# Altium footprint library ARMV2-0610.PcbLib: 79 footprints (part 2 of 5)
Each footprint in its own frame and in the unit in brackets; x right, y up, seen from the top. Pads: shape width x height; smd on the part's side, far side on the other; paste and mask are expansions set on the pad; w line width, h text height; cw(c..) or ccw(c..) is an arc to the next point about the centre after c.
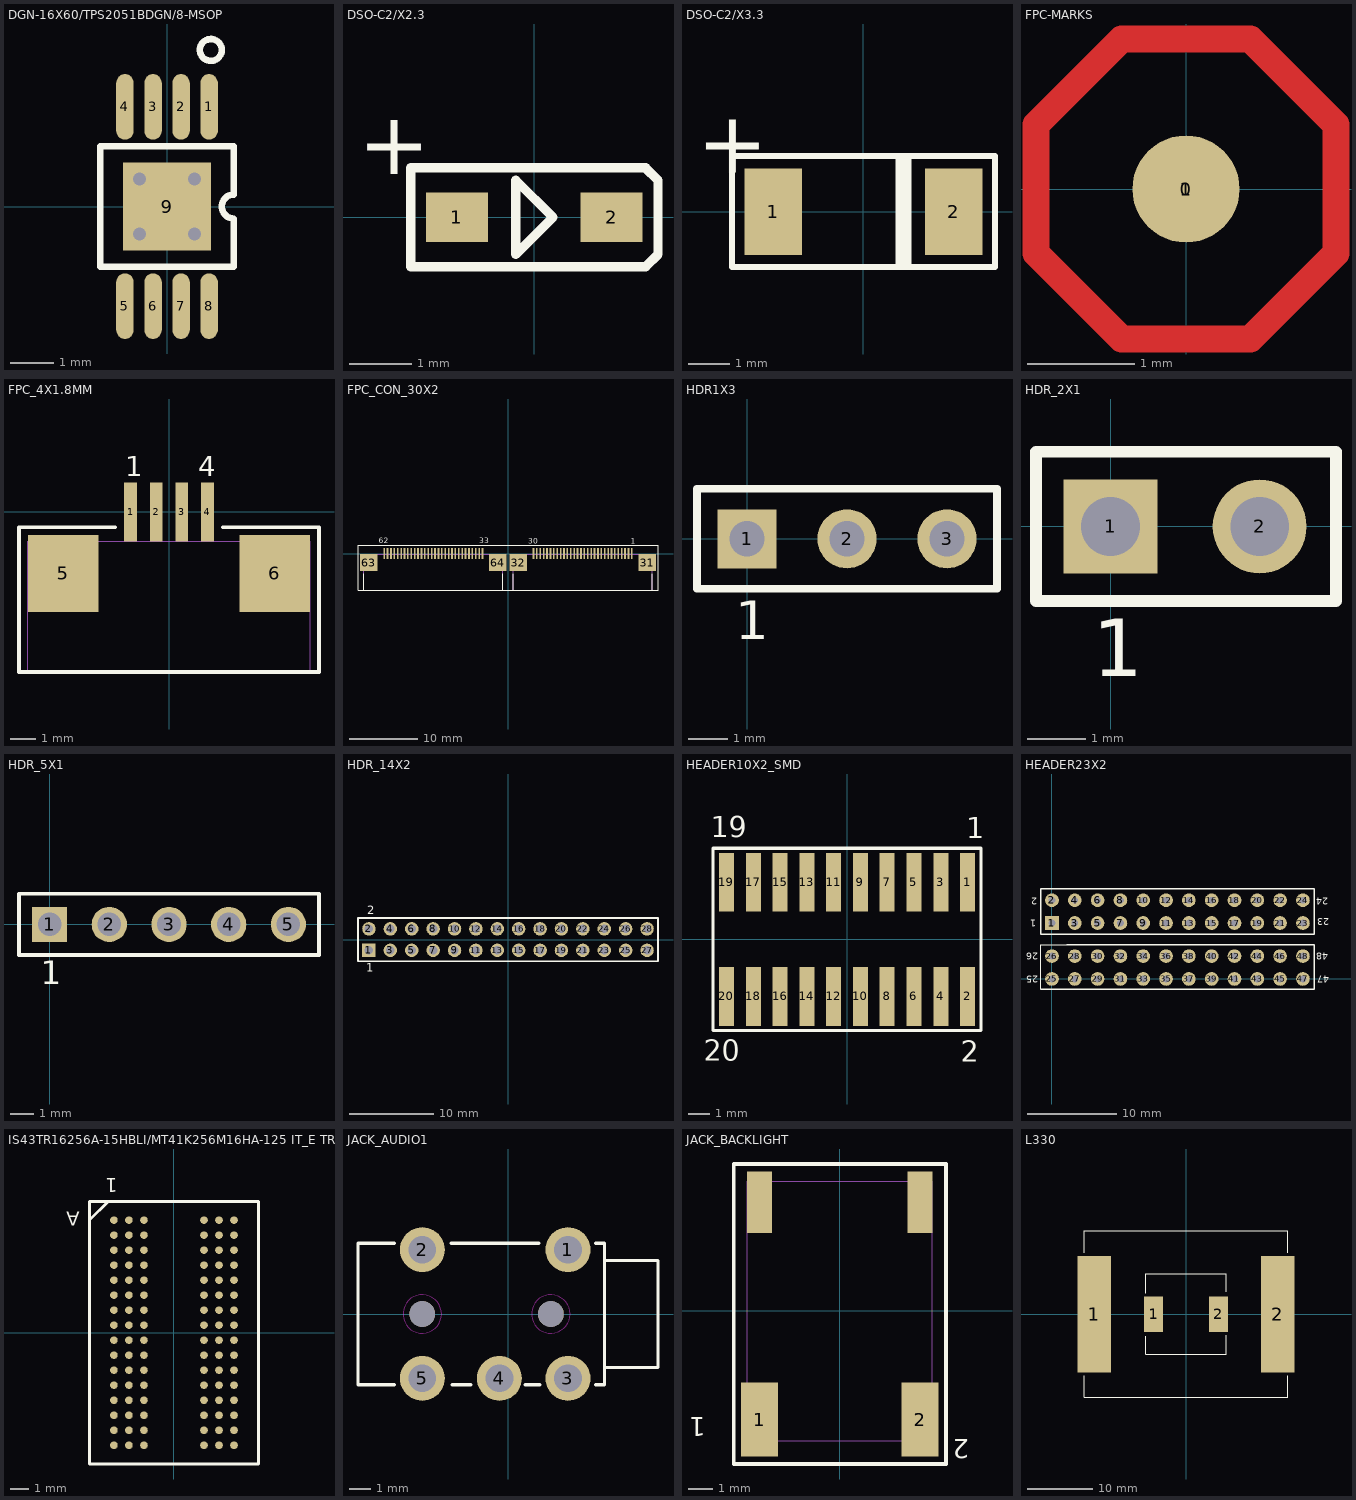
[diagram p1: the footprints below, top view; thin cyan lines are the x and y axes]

## DGN-16X60/TPS2051BDGN/8-MSOP [mil]
pads (9):
  oval 16x60 smd mask+2: 1(38.4,91) 2(12.8,91) 3(-12.8,91) 4(-38.4,91) 5(-38.4,-91) 6(-12.8,-91) 7(12.8,-91) 8(38.4,-91)
  rect 80x80 smd mask+2: 9(0,0)
via 25,25 diameter 22 hole 12
via -25,25 diameter 22 hole 12
via -25,-25 diameter 22 hole 12
via 25,-25 diameter 22 hole 12
Top Overlay:
  circle w6: c40,143 r10
  lines w6: -61.02,-55 -61.02,55 61.02,55 61.02,11 ccw(c61,0) 61,-11 61.02,-55 -61.02,-55

## DSO-C2/X2.3 [mm]
pads (2):
  rect 1x0.8 smd: 1(-1.25,0) 2(1.25,0)
Top Overlay:
  lines w0.152: -2,-0.8 1.8,-0.8 2,-0.6 2,0.6 1.8,0.8 -2,0.8 -2,-0.8 ; -0.3,-0.6 0.3,0 -0.3,0.6 -0.3,-0.6
  text "+" at -2.85,0.7 h1.02

## DSO-C2/X3.3 [mm]
pads (2):
  rect 1.4x2.1 smd: 1(-2.2,0) 2(2.2,0)
Top Overlay:
  lines w0.15: 0.85,-1.35 0.85,1.35 ; 0.95,-1.35 0.95,1.35 ; 1.1,-1.35 1.1,1.35 ; -3.2,-1.35 3.2,-1.35 3.2,1.35 -3.2,1.35 -3.2,-1.35
  text "+" at -4.05,0.95 h1.5

## FPC-MARKS [mm]
pads (2):
  round 2 on Top Solder: 0(0,0)
  round 1 smd: 1(0,0)
Top Layer:
  lines w0.254: -1.4,-0.6 -0.6,-1.4 0.6,-1.4 1.4,-0.6 1.4,0.6 0.6,1.4 0.4,1.4 -0.4,1.4 -0.6,1.4 -1.4,0.6 -1.4,-0.6

## FPC_4X1.8MM [mm] "FPC_4X1.8MM"
pads (6):
  rect 0.5x2.3 smd: 1(-1.5,0) 2(-0.5,0) 3(0.5,0) 4(1.5,0)
  rect 2.75x3 smd: 5(-4.125,-2.4) 6(4.125,-2.4)
Top Overlay:
  lines w0.15: -2.1,-0.6 -5.85,-0.6 -5.85,-6.25 5.85,-6.25 5.85,-0.6 2.1,-0.6
  text "4" at 1.15,1.4 h0.79
  text "1" at -1.7,1.4 h0.79
Mechanical 5:
  lines w0.025: -5.5,-6.25 5.5,-6.25 5.5,-1.15 -5.5,-1.15 -5.5,-6.25

## FPC_CON_30X2 [mm] "FPC_CON_30X2"
pads (64):
  rect 0.25x1.6 smd: 1(18.25,0) 2(17.75,0) 3(17.25,0) 4(16.75,0) 5(16.25,0) 6(15.75,0) 7(15.25,0) 8(14.75,0) 9(14.25,0) 10(13.75,0) 11(13.25,0) 12(12.75,0) 13(12.25,0) 14(11.75,0) 15(11.25,0) 16(10.75,0) 17(10.25,0) 18(9.75,0) 19(9.25,0) 20(8.75,0) 21(8.25,0) 22(7.75,0) 23(7.25,0) 24(6.75,0) 25(6.25,0) 26(5.75,0) 27(5.25,0) 28(4.75,0) 29(4.25,0) 30(3.75,0) 33(-3.75,0) 34(-4.25,0) 35(-4.75,0) 36(-5.25,0) 37(-5.75,0) 38(-6.25,0) 39(-6.75,0) 40(-7.25,0) 41(-7.75,0) 42(-8.25,0) 43(-8.75,0) 44(-9.25,0) 45(-9.75,0) 46(-10.25,0) 47(-10.75,0) 48(-11.25,0) 49(-11.75,0) 50(-12.25,0) 51(-12.75,0) 52(-13.25,0) 53(-13.75,0) 54(-14.25,0) 55(-14.75,0) 56(-15.25,0) 57(-15.75,0) 58(-16.25,0) 59(-16.75,0) 60(-17.25,0) 61(-17.75,0) 62(-18.25,0)
  rect 2.6x2.5 smd: 31(20.5,-1.35) 32(1.5,-1.35) 63(-20.5,-1.35) 64(-1.5,-1.35)
Top Overlay:
  lines w0.15: -21.25,-5.4 -21.25,-3 ; -0.75,-5.4 -0.75,-3 ; 0.75,-5.4 0.75,-3 ; 21.25,-5.4 21.25,-3 ; -22.1,-5.4 -22.1,1.2 22.1,1.2 22.1,-5.4 -22.1,-5.4
  text "33" at -4.25,1.5 h0.79
  text "1" at 18.05,1.4 h0.79
  text "62" at -19.012,1.519 h0.79
  text "30" at 2.95,1.4 h0.79
Mechanical 5:
  lines w0.01: -21.25,-5.4 -21.25,-0.1 -0.75,-0.1 -0.75,-5.4 -21.25,-5.4 ; 0.75,-5.4 21.25,-5.4 21.25,-0.1 0.75,-0.1 0.75,-5.4

## HDR1X3 [mm] "Connector; Header; 3 Position"
pads (3):
  rect 1.5x1.5 hole 0.9: 1(0,0)
  round 1.5 hole 0.9: 2(2.54,0) 3(5.08,0)
Top Overlay:
  lines w0.2: -1.27,-1.27 6.35,-1.27 6.35,1.27 -1.27,1.27 -1.27,-1.27
  text "1" at -0.3,-2.55 h0.98

## HDR_2X1 [mm]
pads (2):
  rect 1.6x1.6 hole 1: 1(0,0)
  round 1.6 hole 1: 2(2.54,0)
Top Overlay:
  lines w0.2: -1.27,-1.27 -1.27,1.27 3.84,1.27 3.84,-1.27 -1.27,-1.27
  text "1" at -0.3,-2.55 h0.98

## HDR_5X1 [mm]
pads (5):
  rect 1.5x1.5 hole 1: 1(0,0)
  round 1.5 hole 1: 2(2.54,0) 3(5.08,0) 4(7.62,0) 5(10.16,0)
Top Overlay:
  lines w0.152: -1.3,-1.3 11.46,-1.3 11.46,1.3 -1.3,1.3 -1.3,-1.3
  text "1" at -0.381,-2.54 h1.02

## HDR_14X2 [mm]
pads (28):
  rect 1.6x1.6 hole 1: 1(-16.51,-1.27)
  round 1.6 hole 1: 2(-16.51,1.27) 3(-13.97,-1.27) 4(-13.97,1.27) 5(-11.43,-1.27) 6(-11.43,1.27) 7(-8.89,-1.27) 8(-8.89,1.27) 9(-6.35,-1.27) 10(-6.35,1.27) 11(-3.81,-1.27) 12(-3.81,1.27) 13(-1.27,-1.27) 14(-1.27,1.27) 15(1.27,-1.27) 16(1.27,1.27) 17(3.81,-1.27) 18(3.81,1.27) 19(6.35,-1.27) 20(6.35,1.27) 21(8.89,-1.27) 22(8.89,1.27) 23(11.43,-1.27) 24(11.43,1.27) 25(13.97,-1.27) 26(13.97,1.27) 27(16.51,-1.27) 28(16.51,1.27)
Top Overlay:
  lines w0.2: -17.81,-2.57 -17.81,2.57 17.81,2.57 17.81,-2.57 -17.81,-2.57
  text "1" at -16.81,-3.82 h0.98
  text "2" at -16.71,2.98 h0.98

## HEADER10X2_SMD [mil] "HEADER10X2_SMD"
pads (20):
  rect 28x110 smd mask+2: 1(225,106.5) 2(225,-106.5) 3(175,106.5) 4(175,-106.5) 5(125,106.5) 6(125,-106.5) 7(75,106.5) 8(75,-106.5) 9(25,106.5) 10(25,-106.5) 11(-25,106.5) 12(-25,-106.5) 13(-75,106.5) 14(-75,-106.5) 15(-125,106.5) 16(-125,-106.5) 17(-175,106.5) 18(-175,-106.5) 19(-225,106.5) 20(-225,-106.5)
Top Overlay:
  lines w6: -250,-170 250,-170 250,170 -250,170 -250,-170
  text "20" at -267.72,-226.38 h38.58
  text "19" at -253.94,190.94 h38.58
  text "2" at 212.6,-228.35 h38.58
  text "1" at 222.44,188.98 h38.58

## HEADER23X2 [mil] "HEADER23X2"
pads (48):
  rect 60x60 hole 30 mask+2: 1(0,245)
  round 60 hole 30 mask+2: 2(0,345) 3(100,245) 4(100,345) 5(200,245) 6(200,345) 7(300,245) 8(300,345) 9(400,245) 10(400,345) 11(500,245) 12(500,345) 13(600,245) 14(600,345) 15(700,245) 16(700,345) 17(800,245) 18(800,345) 19(900,245) 20(900,345) 21(1000,245) 22(1000,345) 23(1100,245) 24(1100,345) 25(0,0) 26(0,100) 27(100,0) 28(100,100) 29(200,0) 30(200,100) 31(300,0) 32(300,100) 33(400,0) 34(400,100) 35(500,0) 36(500,100) 37(600,0) 38(600,100) 39(700,0) 40(700,100) 41(800,0) 42(800,100) 43(900,0) 44(900,100) 45(1000,0) 46(1000,100) 47(1100,0) 48(1100,100)
Top Overlay:
  lines w5: -50,-45 -50,150 65,150
  lines w6: -50,-45 1150,-45 1150,150 65,150 ; -50,195 -50,395 1150,395 1150,195 50,195 -50,195
  text "26" at -60,115 h30
  text "25" at -60,15 h30
  text "47" at 1215,15 h30
  text "48" at 1210,115 h30
  text "23" at 1215,265 h30
  text "24" at 1210,355 h30
  text "2" at -65,355 h30
  text "1" at -70,260 h30

## IS43TR16256A-15HBLI/MT41K256M16HA-125 IT_E TR [mil]
height 47.24
pads (96):
  round 16 smd: A1(-125.98,236.22) A2(-94.49,236.22) A3(-62.99,236.22) A7(62.99,236.22) A8(94.49,236.22) A9(125.98,236.22) B1(-125.98,204.72) B2(-94.49,204.72) B3(-62.99,204.72) B7(62.99,204.72) B8(94.49,204.72) B9(125.98,204.72) C1(-125.98,173.23) C2(-94.49,173.23) C3(-62.99,173.23) C7(62.99,173.23) C8(94.49,173.23) C9(125.98,173.23) D1(-125.98,141.73) D2(-94.49,141.73) D3(-62.99,141.73) D7(62.99,141.73) D8(94.49,141.73) D9(125.98,141.73) E1(-125.98,110.24) E2(-94.49,110.24) E3(-62.99,110.24) E7(62.99,110.24) E8(94.49,110.24) E9(125.98,110.24) F1(-125.98,78.74) F2(-94.49,78.74) F3(-62.99,78.74) F7(62.99,78.74) F8(94.49,78.74) F9(125.98,78.74) G1(-125.98,47.24) G2(-94.49,47.24) G3(-62.99,47.24) G7(62.99,47.24) G8(94.49,47.24) G9(125.98,47.24) H1(-125.98,15.75) H2(-94.49,15.75) H3(-62.99,15.75) H7(62.99,15.75) H8(94.49,15.75) H9(125.98,15.75) J1(-125.98,-15.75) J2(-94.49,-15.75) J3(-62.99,-15.75) J7(62.99,-15.75) J8(94.49,-15.75) J9(125.98,-15.75) K1(-125.98,-47.24) K2(-94.49,-47.24) K3(-62.99,-47.24) K7(62.99,-47.24) K8(94.49,-47.24) K9(125.98,-47.24) L1(-125.98,-78.74) L2(-94.49,-78.74) L3(-62.99,-78.74) L7(62.99,-78.74) L8(94.49,-78.74) L9(125.98,-78.74) M1(-125.98,-110.24) M2(-94.49,-110.24) M3(-62.99,-110.24) M7(62.99,-110.24) M8(94.49,-110.24) M9(125.98,-110.24) N1(-125.98,-141.73) N2(-94.49,-141.73) N3(-62.99,-141.73) N7(62.99,-141.73) N8(94.49,-141.73) N9(125.98,-141.73) P1(-125.98,-173.23) P2(-94.49,-173.23) P3(-62.99,-173.23) P7(62.99,-173.23) P8(94.49,-173.23) P9(125.98,-173.23) R1(-125.98,-204.72) R2(-94.49,-204.72) R3(-62.99,-204.72) R7(62.99,-204.72) R8(94.49,-204.72) R9(125.98,-204.72) T1(-125.98,-236.22) T2(-94.49,-236.22) T3(-62.99,-236.22) T7(62.99,-236.22) T8(94.49,-236.22) T9(125.98,-236.22)
Top Overlay:
  lines w6: -177.17,236.22 -137.8,275.59 ; -177.17,-275.59 -177.17,275.59 177.17,275.59 177.17,-275.59 -177.17,-275.59
  text "1" at -118,323.97 h30
  text "A" at -198,253.97 h30

## JACK_AUDIO1 [mm] "jack_audio1"
pads (7):
  round 2.1 hole 1.3: 1(2.8,3) 2(-4,3) 3(2.8,-3) 4(-0.4,-3) 5(-4,-3)
  round 1.2 hole 1.2 unplated: ""(-4,0) ""(2,0)
Top Overlay:
  lines w0.15: -5.3,-3.3 -7,-3.3 -7,3.3 -5.3,3.3 ; -2.65,3.3 1.45,3.3 ; -2.6,-3.3 -1.725,-3.3 ; 0.8,-3.3 1.5,-3.3 ; 4.1,-3.3 4.5,-3.3 4.5,3.3 4.1,3.3 ; 4.5,-2.5 7,-2.5 7,2.5 4.5,2.5
Keep-Out Layer:
  circle w0.025: c-4,0 r0.9
  circle w0.025: c2,0 r0.9

## JACK_BACKLIGHT [mm] "JACK_BACKLIGHT"
pads (4):
  rect 1.5x3 smd: 1(-3.25,-4.4) 2(3.25,-4.4)
  rect 1x2.5 smd: " "(-3.25,4.4) " "(3.25,4.4)
Top Overlay:
  lines w0.15: -4.3,-6.2 -4.3,5.95 4.3,5.95 4.3,-6.2 -4.3,-6.2
  text "1" at -5.423,-4.303 h0.76
  text "2" at 5.245,-5.192 h0.76
Mechanical 5:
  lines w0.025: -3.75,-5.25 -3.75,5.25 3.75,5.25 3.75,-5.25 -3.75,-5.25

## L330 [mm]
pads (4):
  rect 5.1x17.8 smd: 1(-14,0) 2(14,0)
  rect 2.9x5.4 smd: 1(-4.95,0) 2(4.95,0)
Top Overlay:
  lines w0.15: -15.5,-9.4 -15.5,-12.7 15.5,-12.7 15.5,-9.4 ; -15.5,9.4 -15.5,12.75 15.5,12.75 15.5,9.4
  lines w0.152: -6.15,-3.39 -6.15,-6.15 6.15,-6.15 6.15,-3.2 ; -6.15,3.2 -6.15,6.15 6.15,6.15 6.15,3.39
